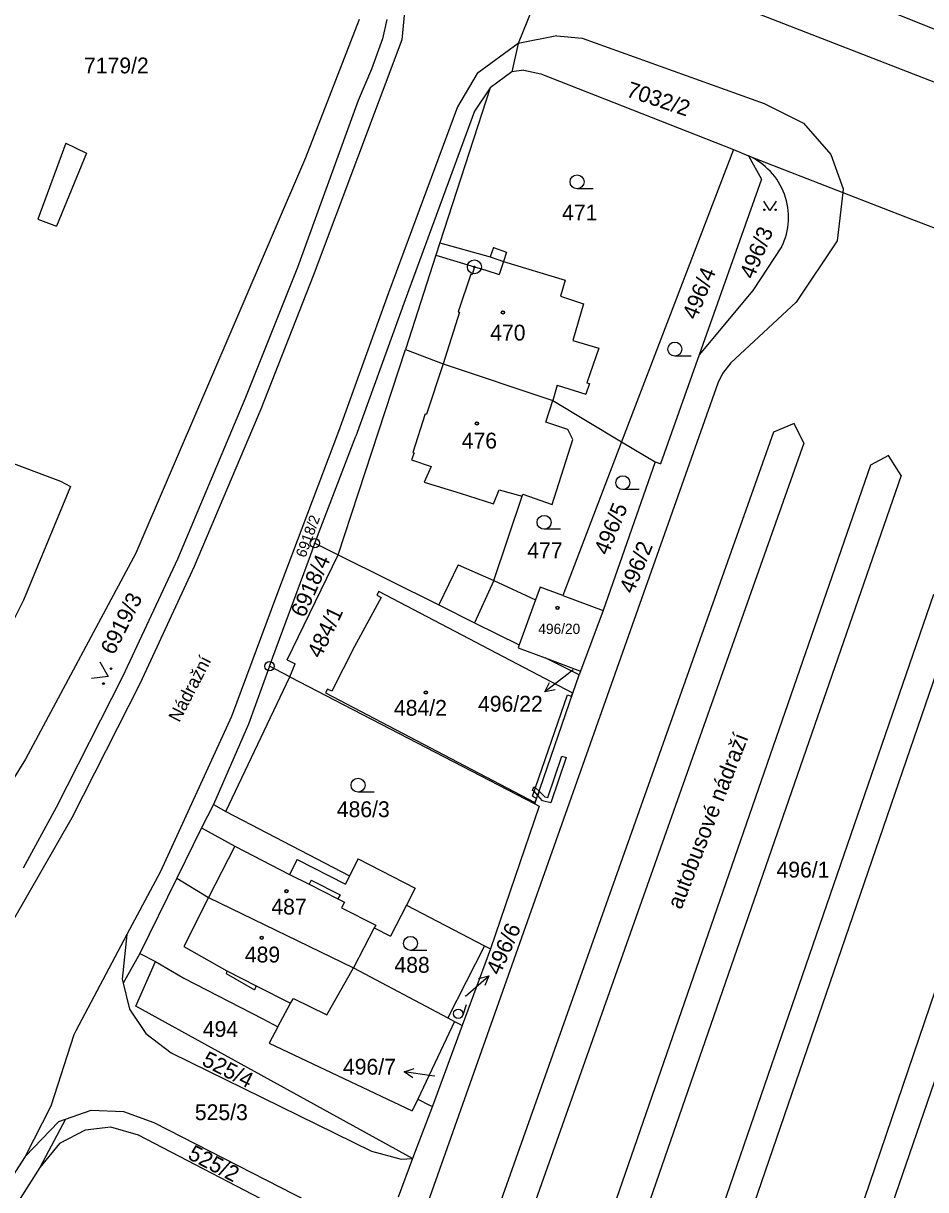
# Model space of a CAD drawing. Extents: x -593183 to -588034, y -1130415 to -1124994.
# Drawn here: x -591438.4 to -591341.4, y -1128361.6 to -1128236.4 of the extents above; entities that cross this region are included whole.
import ezdxf

# ---------------------------------------------------------------- set-up
doc = ezdxf.new("R2010")
doc.units = 0
for name, color, linetype in [('Vrstva 1', 7, 'Continuous'), ('Vrstva 15', 7, 'Continuous'), ('Vrstva 16', 7, 'Continuous'), ('Vrstva 18', 7, 'Continuous'), ('Vrstva 19', 7, 'Continuous'), ('Vrstva 24', 7, 'Continuous'), ('Vrstva 25', 7, 'Continuous'), ('Vrstva 27', 7, 'Continuous'), ('Vrstva 4', 7, 'Continuous')]:
    doc.layers.add(name, color=color, linetype=linetype)

msp = doc.modelspace()

# ---------------------------------------------------------------- linework, layer by layer
at = {"layer": 'Vrstva 1'}
for p, q in [((-591372.57, -1128224.12), (-591340.04, -1128237.17)), ((-591380.28, -1128226.42), (-591385.24, -1128238.52)), ((-591379.17, -1128227.62), (-591291.34, -1128261.84)), ((-591402.3, -1128235.96), (-591408.07, -1128250.81)), ((-591399.34, -1128235.96), (-591399.8, -1128238.01)), ((-591397.43, -1128235.13), (-591397.73, -1128238.12)), ((-591397.73, -1128238.12), (-591407.24, -1128263.47)), ((-591399.8, -1128238.01), (-591400.97, -1128241.29)), ((-591381.08, -1128237.69), (-591385.24, -1128238.52)), ((-591381.08, -1128237.69), (-591378.36, -1128237.94)), ((-591378.36, -1128237.94), (-591358.81, -1128244.98)), ((-591385.24, -1128238.52), (-591389.62, -1128241.75)), ((-591385.24, -1128238.52), (-591385.89, -1128241.56)), ((-591400.97, -1128241.29), (-591402.41, -1128244.65)), ((-591389.62, -1128241.75), (-591391.73, -1128245.31)), ((-591385.89, -1128241.56), (-591388.24, -1128243.27)), ((-591384.61, -1128241.4), (-591385.89, -1128241.56)), ((-591384.61, -1128241.4), (-591382.78, -1128241.79)), ((-591382.78, -1128241.79), (-591362.09, -1128249.9)), ((-591388.24, -1128243.27), (-591393.63, -1128259.92)), ((-591402.41, -1128244.65), (-591408.95, -1128262.58)), ((-591391.73, -1128245.31), (-591399.17, -1128265.32)), ((-591358.81, -1128244.98), (-591354.56, -1128247.09)), ((-591354.56, -1128247.09), (-591351.63, -1128250.46)), ((-591408.07, -1128250.81), (-591426.29, -1128293.28)), ((-591362.09, -1128249.9), (-591374.12, -1128281.32)), ((-591362.09, -1128249.9), (-591360.49, -1128250.59)), ((-591360.49, -1128250.59), (-591359.08, -1128253.1)), ((-591360.49, -1128250.59), (-591350.36, -1128254.52)), ((-591351.63, -1128250.46), (-591350.31, -1128254.12)), ((-591359.08, -1128253.1), (-591361.22, -1128259.14)), ((-591350.36, -1128254.52), (-591350.96, -1128259.71)), ((-591350.31, -1128254.12), (-591350.36, -1128254.52)), ((-591350.36, -1128254.52), (-591342.96, -1128257.39)), ((-591342.96, -1128257.39), (-591334.78, -1128260.49)), ((-591361.22, -1128259.14), (-591365.78, -1128271.96)), ((-591350.96, -1128259.71), (-591355.37, -1128266.31)), ((-591393.63, -1128259.92), (-591394.06, -1128261.25)), ((-591393.63, -1128259.92), (-591388.23, -1128261.45)), ((-591387.89, -1128260.45), (-591388.23, -1128261.45)), ((-591387.89, -1128260.45), (-591386.47, -1128260.92)), ((-591386.47, -1128260.92), (-591386.81, -1128261.93)), ((-591356.92, -1128260.38), (-591360.02, -1128265.07)), ((-591394.06, -1128261.25), (-591397.34, -1128271.4)), ((-591386.81, -1128261.93), (-591380.17, -1128263.94)), ((-591408.95, -1128262.58), (-591414.6, -1128276.72)), ((-591407.24, -1128263.47), (-591412.86, -1128277.79)), ((-591380.17, -1128263.94), (-591380.67, -1128265.66)), ((-591399.17, -1128265.32), (-591404.53, -1128280.2)), ((-591380.67, -1128265.66), (-591378.19, -1128266.49)), ((-591360.02, -1128265.07), (-591365.78, -1128271.96)), ((-591378.19, -1128266.49), (-591379.36, -1128270.42)), ((-591355.37, -1128266.31), (-591362.39, -1128272.84)), ((-591379.36, -1128270.42), (-591376.56, -1128271.25)), ((-591404.56, -1128293.45), (-591397.34, -1128271.4)), ((-591397.34, -1128271.4), (-591393.27, -1128272.95)), ((-591376.56, -1128271.25), (-591377.85, -1128274.96)), ((-591365.78, -1128271.96), (-591369.93, -1128283.66)), ((-591393.27, -1128272.95), (-591381.49, -1128276.88)), ((-591362.39, -1128272.84), (-591363.29, -1128273.97)), ((-591363.29, -1128273.97), (-591363.78, -1128275)), ((-591363.78, -1128275), (-591395.11, -1128363.53)), ((-591381.02, -1128275.24), (-591381.49, -1128276.88)), ((-591381.02, -1128275.24), (-591377.96, -1128276.2)), ((-591377.56, -1128275.06), (-591377.96, -1128276.2)), ((-591377.85, -1128274.96), (-591377.56, -1128275.06)), ((-591414.6, -1128276.72), (-591421.83, -1128293.92)), ((-591382.24, -1128279.21), (-591381.49, -1128276.88)), ((-591381.49, -1128276.88), (-591374.12, -1128281.32)), ((-591412.86, -1128277.79), (-591420.05, -1128294.7)), ((-591379.88, -1128279.99), (-591382.24, -1128279.21)), ((-591404.53, -1128280.2), (-591411.18, -1128297.81)), ((-591381.56, -1128288.03), (-591379.36, -1128281.05)), ((-591379.36, -1128281.05), (-591379.88, -1128279.99)), ((-591443.14, -1128282.26), (-591434.41, -1128285.52)), ((-591374.12, -1128281.32), (-591380.44, -1128297.83)), ((-591374.12, -1128281.32), (-591370.49, -1128283.46)), ((-591370.49, -1128283.46), (-591376.1, -1128299.43)), ((-591370.49, -1128283.46), (-591370.18, -1128283.57)), ((-591370.18, -1128283.57), (-591369.93, -1128283.66)), ((-591434.41, -1128285.52), (-591433.33, -1128286.1)), ((-591433.33, -1128286.1), (-591438.38, -1128298.33)), ((-591387.83, -1128296.22), (-591384.81, -1128287.16)), ((-591384.81, -1128287.16), (-591384.73, -1128286.92)), ((-591384.73, -1128286.92), (-591381.56, -1128288.03)), ((-591407.07, -1128292.21), (-591404.56, -1128293.45)), ((-591426.29, -1128293.28), (-591438.14, -1128315.41)), ((-591410.03, -1128304.74), (-591404.56, -1128293.45)), ((-591404.56, -1128293.45), (-591393.76, -1128298.84)), ((-591421.83, -1128293.92), (-591427.72, -1128306.55)), ((-591420.05, -1128294.7), (-591425.85, -1128307.25)), ((-591387.83, -1128296.22), (-591383.35, -1128298.27)), ((-591382.87, -1128296.94), (-591383.35, -1128298.27)), ((-591380.44, -1128297.83), (-591382.87, -1128296.94)), ((-591438.38, -1128298.33), (-591439.84, -1128301.27)), ((-591411.18, -1128297.81), (-591416.02, -1128310.83)), ((-591399.96, -1128298.02), (-591402.82, -1128303.29)), ((-591400.19, -1128297.39), (-591400.4, -1128297.79)), ((-591400.4, -1128297.79), (-591399.96, -1128298.02)), ((-591379.34, -1128308.31), (-591400.19, -1128297.39)), ((-591383.35, -1128298.27), (-591385.12, -1128303.13)), ((-591380.44, -1128297.83), (-591376.1, -1128299.43)), ((-591393.76, -1128298.84), (-591389.93, -1128300.75)), ((-591376.1, -1128299.43), (-591378.52, -1128305.94)), ((-591389.93, -1128300.75), (-591385.12, -1128303.13)), ((-591402.82, -1128303.29), (-591405.26, -1128308.11)), ((-591385.12, -1128303.13), (-591385.23, -1128303.44)), ((-591385.23, -1128303.44), (-591382.32, -1128304.53)), ((-591410.03, -1128304.74), (-591409.2, -1128305.15)), ((-591382.32, -1128304.53), (-591378.52, -1128305.94)), ((-591378.67, -1128306.34), (-591382.32, -1128304.53)), ((-591409.75, -1128306.55), (-591411.93, -1128305.42)), ((-591409.75, -1128306.55), (-591409.2, -1128305.15)), ((-591378.52, -1128305.94), (-591378.67, -1128306.34)), ((-591427.72, -1128306.55), (-591434.85, -1128320.58)), ((-591425.85, -1128307.25), (-591433.19, -1128321.7)), ((-591416.63, -1128321.02), (-591409.75, -1128306.55)), ((-591409.75, -1128306.55), (-591383.43, -1128320.21)), ((-591379.34, -1128308.31), (-591378.67, -1128306.34)), ((-591405.7, -1128307.88), (-591405.91, -1128308.28)), ((-591405.91, -1128308.28), (-591383.42, -1128320.06)), ((-591405.26, -1128308.11), (-591405.7, -1128307.88)), ((-591383.25, -1128319.68), (-591379.34, -1128308.31)), ((-591329.98, -1128309.46), (-591353.39, -1128378.36)), ((-591416.02, -1128310.83), (-591423.67, -1128327.47)), ((-591438.14, -1128315.41), (-591449.87, -1128334.09)), ((-591383.43, -1128320.21), (-591383.25, -1128319.68)), ((-591383.42, -1128320.06), (-591383.25, -1128319.68)), ((-591434.85, -1128320.58), (-591438.4, -1128327.1)), ((-591417.97, -1128320.26), (-591419.26, -1128322.77)), ((-591417.97, -1128320.26), (-591416.63, -1128321.02)), ((-591416.63, -1128321.02), (-591403.33, -1128327.92)), ((-591382.98, -1128320.44), (-591388.19, -1128335.78)), ((-591383.43, -1128320.21), (-591382.98, -1128320.44)), ((-591433.19, -1128321.7), (-591446.93, -1128345.63)), ((-591419.26, -1128322.77), (-591421.89, -1128328.17)), ((-591402.4, -1128326.11), (-591403.33, -1128327.92)), ((-591402.4, -1128326.11), (-591396.28, -1128329.25)), ((-591423.67, -1128327.47), (-591427.27, -1128334.25)), ((-591421.89, -1128328.17), (-591425.88, -1128336.27)), ((-591421.89, -1128328.17), (-591418.48, -1128330.27)), ((-591396.28, -1128329.25), (-591397.23, -1128331.09)), ((-591418.48, -1128330.27), (-591402.93, -1128337.82)), ((-591397.23, -1128331.09), (-591398.94, -1128334.43)), ((-591397.23, -1128331.09), (-591388.83, -1128335.45)), ((-591400.68, -1128333.53), (-591402.93, -1128337.82)), ((-591400.68, -1128333.53), (-591398.94, -1128334.43)), ((-591427.27, -1128334.25), (-591432.76, -1128344.6)), ((-591427.27, -1128334.25), (-591427.77, -1128339.02)), ((-591388.83, -1128335.45), (-591392.78, -1128343.19)), ((-591388.19, -1128335.78), (-591391.23, -1128344.01)), ((-591388.83, -1128335.45), (-591388.19, -1128335.78)), ((-591425.88, -1128336.27), (-591427.66, -1128339.48)), ((-591426.3, -1128341.95), (-591424.2, -1128337.15)), ((-591425.88, -1128336.27), (-591424.2, -1128337.15)), ((-591424.2, -1128337.15), (-591421.16, -1128338.93)), ((-591402.93, -1128337.82), (-591392.78, -1128343.19)), ((-591427.77, -1128339.02), (-591427.66, -1128339.48)), ((-591427.66, -1128339.48), (-591426.98, -1128342.26)), ((-591421.16, -1128338.93), (-591412.67, -1128343.3)), ((-591426.98, -1128342.26), (-591425.22, -1128344.86)), ((-591396.57, -1128358.29), (-591426.3, -1128341.95)), ((-591412.67, -1128343.3), (-591411.05, -1128344.14)), ((-591392.05, -1128343.58), (-591396, -1128351.92)), ((-591392.78, -1128343.19), (-591392.05, -1128343.58)), ((-591392.05, -1128343.58), (-591391.57, -1128343.83)), ((-591432.76, -1128344.6), (-591432.98, -1128345.02)), ((-591425.22, -1128344.86), (-591422.5, -1128346.95)), ((-591411.05, -1128344.14), (-591411.99, -1128345.9)), ((-591391.23, -1128344.01), (-591394.43, -1128352.69)), ((-591391.57, -1128343.83), (-591391.23, -1128344.01)), ((-591432.98, -1128345.02), (-591435.44, -1128352.69)), ((-591411.99, -1128345.9), (-591396.6, -1128353.19)), ((-591422.5, -1128346.95), (-591400.98, -1128357.52)), ((-591396, -1128351.92), (-591396.6, -1128353.19)), ((-591396, -1128351.92), (-591394.69, -1128352.6)), ((-591435.44, -1128352.69), (-591438.2, -1128358.07)), ((-591433.86, -1128354.08), (-591431.11, -1128353.11)), ((-591431.11, -1128353.11), (-591427.62, -1128353.24)), ((-591427.62, -1128353.24), (-591424.36, -1128354.44)), ((-591394.43, -1128352.69), (-591396.57, -1128358.29)), ((-591394.69, -1128352.6), (-591394.43, -1128352.69)), ((-591438.2, -1128358.07), (-591434.57, -1128354.33)), ((-591433.86, -1128354.08), (-591436.62, -1128359.26)), ((-591434.57, -1128354.33), (-591433.86, -1128354.08)), ((-591428.98, -1128354.92), (-591431.73, -1128355.26)), ((-591426.01, -1128355.79), (-591428.98, -1128354.92)), ((-591424.36, -1128354.44), (-591399.72, -1128367.02)), ((-591431.73, -1128355.26), (-591434.49, -1128356.68)), ((-591403.01, -1128367.74), (-591426.01, -1128355.79)), ((-591434.49, -1128356.68), (-591436.62, -1128359.26)), ((-591438.2, -1128358.07), (-591450.68, -1128377.51)), ((-591400.98, -1128357.52), (-591397.78, -1128358.38)), ((-591396.57, -1128358.29), (-591398.12, -1128362.46)), ((-591397.78, -1128358.38), (-591396.57, -1128358.29)), ((-591436.62, -1128359.26), (-591449.06, -1128378.79))]:
    msp.add_line(p, q, dxfattribs=at)
msp.add_lwpolyline([(-591411.93, -1128305.42), (-591407.55, -1128293.53), (-591407.07, -1128292.21)], dxfattribs=at)
msp.add_arc((-591363.38, -1128257.19), 7.2, 333.708, 66.3616, dxfattribs=at)
at = {"layer": 'Vrstva 16'}
for p, q in [((-591379.31, -1128305.82), (-591379.98, -1128306.33)), ((-591390.88, -1128340.86), (-591390.65, -1128340.66)), ((-591394.19, -1128349.47), (-591394.5, -1128349.42))]:
    msp.add_line(p, q, dxfattribs=at)
at = {"layer": 'Vrstva 24'}
for centre, radius in [((-591389.93, -1128262.52), 0.75), ((-591389.93, -1128262.52), 0.0903), ((-591407.07, -1128292.21), 0.5), ((-591407.07, -1128292.21), 0.0327), ((-591411.93, -1128305.42), 0.5), ((-591411.93, -1128305.42), 0.0327)]:
    msp.add_circle(centre, radius, dxfattribs=at)
at = {"layer": 'Vrstva 25'}
for p, q in [((-591377.15, -1128254.13), (-591378.9, -1128254.13)), ((-591366.65, -1128272.1), (-591368.4, -1128272.1)), ((-591372.23, -1128286.45), (-591373.98, -1128286.45)), ((-591380.69, -1128290.71), (-591382.44, -1128290.71)), ((-591379.98, -1128306.33), (-591382.36, -1128308.16)), ((-591400.68, -1128318.95), (-591402.43, -1128318.95)), ((-591395.05, -1128335.94), (-591396.8, -1128335.94)), ((-591390.65, -1128340.66), (-591388.39, -1128338.68)), ((-591390.82, -1128341.79), (-591391.18, -1128342.91)), ((-591394.5, -1128349.42), (-591397.47, -1128348.98))]:
    msp.add_line(p, q, dxfattribs=at)
for points in [[(-591357.5, -1128255.45), (-591358.17, -1128256.45), (-591358.84, -1128255.45)], [(-591430.17, -1128304.96), (-591429.28, -1128306.53), (-591431.07, -1128306.75)], [(-591381.26, -1128307.94), (-591382.36, -1128308.16), (-591381.87, -1128307.15)], [(-591389.47, -1128338.97), (-591388.39, -1128338.68), (-591388.82, -1128339.72)], [(-591396.55, -1128349.62), (-591397.47, -1128348.98), (-591396.4, -1128348.63)]]:
    msp.add_lwpolyline(points, dxfattribs=at)
for centre, radius in [((-591378.9, -1128253.38), 0.75), ((-591358.77, -1128256.38), 0.067), ((-591357.57, -1128256.38), 0.067), ((-591386.86, -1128267.41), 0.175), ((-591386.86, -1128267.41), 0.15), ((-591368.4, -1128271.35), 0.75), ((-591389.66, -1128279.34), 0.175), ((-591389.66, -1128279.34), 0.15), ((-591373.98, -1128285.7), 0.75), ((-591382.44, -1128289.96), 0.75), ((-591381, -1128299.15), 0.175), ((-591381, -1128299.15), 0.15), ((-591428.97, -1128305.68), 0.1), ((-591429.77, -1128307.29), 0.1), ((-591395.15, -1128308.24), 0.175), ((-591395.15, -1128308.24), 0.15), ((-591402.43, -1128318.2), 0.75), ((-591410.12, -1128329.59), 0.175), ((-591410.12, -1128329.59), 0.15), ((-591412.78, -1128334.59), 0.175), ((-591412.78, -1128334.59), 0.15), ((-591396.8, -1128335.19), 0.75), ((-591391.66, -1128342.75), 0.503)]:
    msp.add_circle(centre, radius, dxfattribs=at)
at = {"layer": 'Vrstva 27'}
for p, q in [((-591382.03, -1128319.51), (-591380.54, -1128315.07)), ((-591380.06, -1128315.23), (-591381.71, -1128320.09)), ((-591380.54, -1128315.07), (-591380.06, -1128315.23)), ((-591383.69, -1128318.77), (-591383.56, -1128318.39)), ((-591383.56, -1128318.39), (-591383.36, -1128318.47)), ((-591383.36, -1128318.47), (-591382.96, -1128318.85)), ((-591383.49, -1128318.85), (-591383.69, -1128318.77)), ((-591383.11, -1128319.29), (-591383.49, -1128318.85)), ((-591382.96, -1128318.85), (-591383.11, -1128319.29)), ((-591383.11, -1128319.29), (-591382.96, -1128318.85)), ((-591382.61, -1128319.89), (-591383.11, -1128319.29)), ((-591382.96, -1128318.85), (-591382.35, -1128319.43)), ((-591381.71, -1128320.09), (-591382.61, -1128319.89)), ((-591382.35, -1128319.43), (-591382.03, -1128319.51))]:
    msp.add_line(p, q, dxfattribs=at)
at = {"layer": 'Vrstva 4'}
for p, q in [((-591388.24, -1128243.27), (-591389.92, -1128245.79)), ((-591389.92, -1128245.79), (-591397.38, -1128266.05)), ((-591433.81, -1128249.23), (-591436.83, -1128257.39)), ((-591433.81, -1128249.23), (-591431.6, -1128250.29)), ((-591431.6, -1128250.29), (-591434.81, -1128258.16)), ((-591436.83, -1128257.39), (-591434.81, -1128258.16)), ((-591394.06, -1128261.25), (-591389.93, -1128262.52)), ((-591388.23, -1128261.45), (-591386.81, -1128261.93)), ((-591386.81, -1128261.93), (-591387.28, -1128263.35)), ((-591390.3, -1128263.3), (-591391.66, -1128267.35)), ((-591390.3, -1128263.3), (-591390.16, -1128263.35)), ((-591389.93, -1128262.52), (-591390.16, -1128263.35)), ((-591389.93, -1128262.52), (-591388.7, -1128262.87)), ((-591388.7, -1128262.87), (-591387.28, -1128263.35)), ((-591397.38, -1128266.05), (-591402.68, -1128280.72)), ((-591391.52, -1128267.4), (-591393.27, -1128272.95)), ((-591391.66, -1128267.35), (-591391.52, -1128267.4)), ((-591393.27, -1128272.95), (-591395.08, -1128278.35)), ((-591395.22, -1128278.3), (-591396.54, -1128282.47)), ((-591395.22, -1128278.3), (-591395.08, -1128278.35)), ((-591355.59, -1128279.33), (-591357.81, -1128280.29)), ((-591354.53, -1128281.45), (-591355.59, -1128279.33)), ((-591407.07, -1128292.21), (-591402.68, -1128280.72)), ((-591357.81, -1128280.29), (-591388.21, -1128365.98)), ((-591354.53, -1128281.45), (-591384.91, -1128367.16)), ((-591396.39, -1128282.51), (-591396.67, -1128283.24)), ((-591396.67, -1128283.24), (-591394.57, -1128283.98)), ((-591396.54, -1128282.47), (-591396.39, -1128282.51)), ((-591345.44, -1128282.77), (-591347.37, -1128283.83)), ((-591344.08, -1128284.94), (-591345.44, -1128282.77)), ((-591394.57, -1128283.98), (-591395.33, -1128285.66)), ((-591347.37, -1128283.83), (-591377.21, -1128369.89)), ((-591395.33, -1128285.66), (-591391.46, -1128286.84)), ((-591344.08, -1128284.94), (-591373.95, -1128371.05)), ((-591391.46, -1128286.84), (-591387.88, -1128287.96)), ((-591387.88, -1128287.96), (-591387.26, -1128286.46)), ((-591387.26, -1128286.46), (-591384.81, -1128287.16)), ((-591391.68, -1128294.52), (-591393.76, -1128298.84)), ((-591391.68, -1128294.52), (-591387.83, -1128296.22)), ((-591387.83, -1128296.22), (-591389.93, -1128300.75)), ((-591340.59, -1128297.72), (-591366.77, -1128373.6)), ((-591337.84, -1128298.88), (-591363.83, -1128374.65)), ((-591411.93, -1128305.42), (-591414.21, -1128311.65)), ((-591383.67, -1128319.38), (-591379.94, -1128308.5)), ((-591379.94, -1128308.5), (-591379.53, -1128308.62)), ((-591379.53, -1128308.62), (-591379.34, -1128308.31)), ((-591414.21, -1128311.65), (-591417.97, -1128320.26)), ((-591327.2, -1128311.21), (-591350.58, -1128379.36)), ((-591383.25, -1128319.68), (-591383.67, -1128319.38)), ((-591419.26, -1128322.77), (-591415.68, -1128324.76)), ((-591415.68, -1128324.76), (-591418.48, -1128330.27)), ((-591415.68, -1128324.76), (-591409.79, -1128327.78)), ((-591408.97, -1128326.18), (-591409.79, -1128327.78)), ((-591408.97, -1128326.18), (-591403.79, -1128328.83)), ((-591409.79, -1128327.78), (-591407.67, -1128328.83)), ((-591407.46, -1128328.39), (-591407.67, -1128328.83)), ((-591407.46, -1128328.39), (-591404.35, -1128329.98)), ((-591403.33, -1128327.92), (-591403.79, -1128328.83)), ((-591407.67, -1128328.83), (-591404.6, -1128330.39)), ((-591418.48, -1128330.27), (-591421.13, -1128335.51)), ((-591404.35, -1128329.98), (-591404.6, -1128330.39)), ((-591404.6, -1128330.39), (-591403.89, -1128330.75)), ((-591403.89, -1128330.75), (-591404.2, -1128331.37)), ((-591404.2, -1128331.37), (-591400.52, -1128333.22)), ((-591400.52, -1128333.22), (-591400.68, -1128333.53)), ((-591421.13, -1128335.51), (-591416.52, -1128338.13)), ((-591416.52, -1128338.13), (-591416.59, -1128338.44)), ((-591416.59, -1128338.44), (-591413.57, -1128340.18)), ((-591416.52, -1128338.13), (-591413.36, -1128339.75)), ((-591405.77, -1128342.87), (-591402.93, -1128337.82)), ((-591413.36, -1128339.75), (-591413.57, -1128340.18)), ((-591413.36, -1128339.75), (-591409.7, -1128341.62)), ((-591409.7, -1128341.62), (-591409.37, -1128341.1)), ((-591409.37, -1128341.1), (-591405.77, -1128342.87)), ((-591411.05, -1128344.14), (-591409.7, -1128341.62))]:
    msp.add_line(p, q, dxfattribs=at)

# ---------------------------------------------------------------- texts
at = {"layer": 'Vrstva 15'}
for s, height, rotation, p in [('Nádražní', 1.4, 62.6761, (-591421.63, -1128311.53)), ('autobusové nádraží', 1.7, 68.7215, (-591367.7, -1128331.63))]:
    msp.add_text(s, height=height, rotation=rotation, dxfattribs=at).set_placement(p)
at = {"layer": 'Vrstva 16'}
for s, p in [('496/22', (-591389.54, -1128310.3)), ('496/7', (-591404.05, -1128349.29))]:
    msp.add_text(s, height=1.7, dxfattribs=at).set_placement(p)
msp.add_text('496/6', height=1.7, rotation=66.1478, dxfattribs=at).set_placement((-591387.19, -1128338.71))
at = {"layer": 'Vrstva 18'}
for s, height, p in [('7179/2', 1.7, (-591431.87, -1128241.73)), ('471', 1.7, (-591380.51, -1128257.53)), ('477', 1.7, (-591384.25, -1128293.82)), ('496/22', 0.01, (-591379.31, -1128305.82)), ('486/3', 1.7, (-591404.71, -1128321.63)), ('496/1', 1.7, (-591357.47, -1128328.12)), ('488', 1.7, (-591398.52, -1128338.35)), ('496/6', 0.1, (-591391.06, -1128340.86)), ('494', 1.7, (-591419.11, -1128345.24)), ('496/7', 0.01, (-591394.19, -1128349.47)), ('525/3', 1.7, (-591419.96, -1128354.18))]:
    msp.add_text(s, height=height, dxfattribs=at).set_placement(p)
for s, height, rotation, p in [('7032/2', 1.7, 341.565, (-591373.71, -1128244.18)), ('496/3', 1.7, 67.8905, (-591359.93, -1128263.93)), ('496/4', 1.7, 67.8905, (-591366.08, -1128268.29)), ('496/5', 1.7, 67.8905, (-591375.57, -1128293.59)), ('6918/2', 1.14, 69.8984, (-591408.09, -1128293.83)), ('496/2', 1.7, 67.8905, (-591372.86, -1128297.72)), ('6918/4', 1.7, 66.068, (-591408.18, -1128300.29)), ('6919/3', 1.7, 63.435, (-591428.66, -1128304.3)), ('484/1', 1.7, 64.3118, (-591406.45, -1128304.67)), ('525/4', 1.7, 332.9125, (-591419.32, -1128348.21)), ('525/2', 1.7, 332.5924, (-591420.83, -1128358.27))]:
    msp.add_text(s, height=height, rotation=rotation, dxfattribs=at).set_placement(p)
at = {"layer": 'Vrstva 19'}
for s, height, p in [('470', 1.7, (-591388.23, -1128270.43)), ('476', 1.7, (-591391.29, -1128282.03)), ('496/20', 1.1, (-591383.06, -1128301.95)), ('484/2', 1.7, (-591398.57, -1128310.74)), ('487', 1.7, (-591411.74, -1128332.09)), ('489', 1.7, (-591414.59, -1128337.24))]:
    msp.add_text(s, height=height, dxfattribs=at).set_placement(p)

doc.saveas('drawing.dxf')
